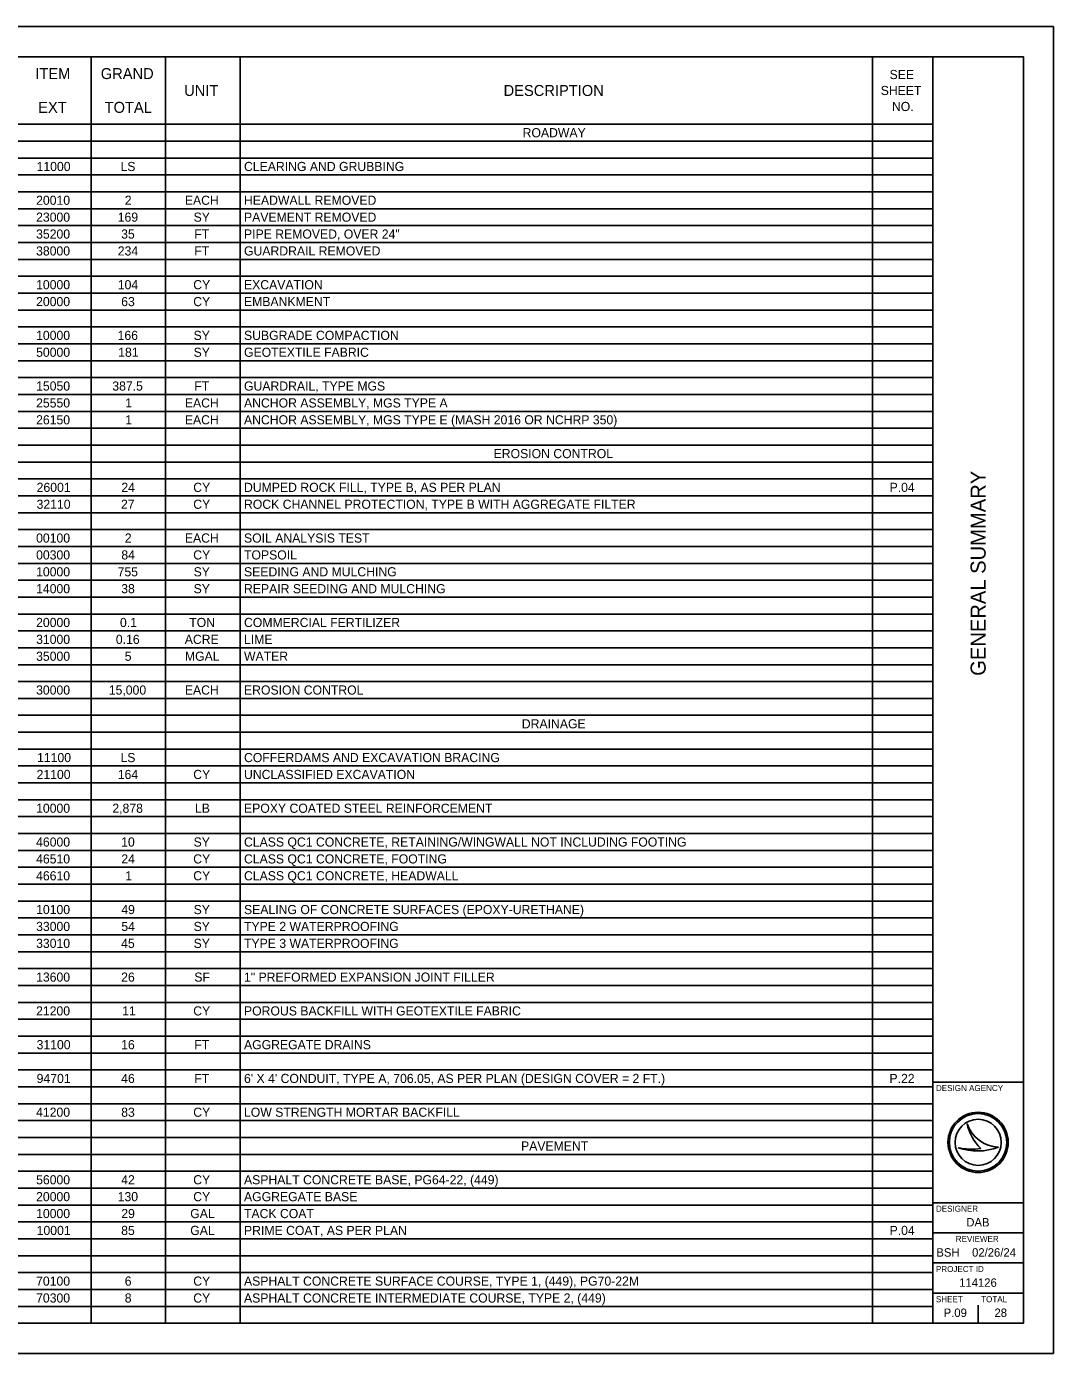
# Model space of a CAD drawing. Extents: x 0 to 34, y 0 to 22.
# Drawn here: x 16.96 to 34, y 0 to 22 of the extents above; entities that cross this region are included whole.
import ezdxf

# ---------------------------------------------------------------- set-up
doc = ezdxf.new("R2010")
doc.units = 0
for name, color, linetype in [('SH_Border', 7, 'Continuous'), ('SH_Cut_Line', 7, 'Continuous'), ('SH_Data', 7, 'Continuous'), ('SH_Text', 7, 'Continuous')]:
    doc.layers.add(name, color=color, linetype=linetype)

msp = doc.modelspace()

# ---------------------------------------------------------------- linework, layer by layer
at = {"layer": 'SH_Border'}
for p, q in [((32, 0.5), (32, 21.5)), ((32, 4.5), (33.5, 4.5)), ((32, 2.5), (33.5, 2.5)), ((32, 2), (33.5, 2)), ((32, 1.5), (33.5, 1.5)), ((32, 1), (33.5, 1))]:
    msp.add_line(p, q, dxfattribs=at)
msp.add_lwpolyline([(1.5, 21.5), (33.5, 21.5), (33.5, 0.5), (1.5, 0.5)], close=True, dxfattribs=at)
at = {"layer": 'SH_Cut_Line'}
msp.add_lwpolyline([(0, 0), (34, 0), (34, 22), (0, 22)], close=True, dxfattribs=at)
at = {"layer": 'SH_Data'}
for p, q in [((32.567, 3.81), (32.567, 3.81)), ((32.417, 3.41), (32.417, 3.41)), ((32.75, 3.5), (32.75, 3.5)), ((33.087, 3.419), (33.087, 3.419)), ((32.375, 0.675), (32.375, 0.675)), ((32.75, 0.5), (32.75, 0.8))]:
    msp.add_line(p, q, dxfattribs=at)
for radius in [0.5, 0.477, 0.477, 0.382]:
    msp.add_circle((32.75, 3.5), radius, dxfattribs=at)
for centre, radius, start, end in [((33.116, 3.998), 0.58, 198.9257, 198.9319), ((33.347, 3.97), 0.796, 191.6379, 191.6421), ((33.116, 3.998), 0.58, 198.9319, 267.1657), ((33.347, 3.97), 0.796, 191.6421, 226.0947), ((32.739, 4.37), 1.013, 251.4576, 290.0832), ((32.648, 4.654), 1.266, 259.4964, 259.4995), ((32.739, 4.37), 1.013, 251.4527, 251.4576), ((32.648, 4.654), 1.266, 259.4995, 276.6672)]:
    msp.add_arc(centre, radius, start, end, dxfattribs=at)
at = {"layer": 'SH_Text'}
for p, q in [((1.5, 21.5), (32, 21.5)), ((18.035, 21.5), (18.035, 0.5)), ((19.27, 21.5), (19.27, 0.5)), ((20.505, 21.5), (20.505, 0.5)), ((30.995, 21.5), (30.995, 0.5)), ((32, 21.5), (32, 0.5)), ((1.5, 20.38), (32, 20.38)), ((1.5, 20.1), (32, 20.1)), ((1.5, 19.82), (32, 19.82)), ((1.5, 19.54), (32, 19.54)), ((1.5, 19.26), (32, 19.26)), ((1.5, 18.98), (32, 18.98)), ((1.5, 18.7), (32, 18.7)), ((1.5, 18.42), (32, 18.42)), ((1.5, 18.14), (32, 18.14)), ((1.5, 17.86), (32, 17.86)), ((1.5, 17.58), (32, 17.58)), ((1.5, 17.3), (32, 17.3)), ((1.5, 17.02), (32, 17.02)), ((1.5, 16.74), (32, 16.74)), ((1.5, 16.46), (32, 16.46)), ((1.5, 16.18), (32, 16.18)), ((1.5, 15.9), (32, 15.9)), ((1.5, 15.62), (32, 15.62)), ((1.5, 15.34), (32, 15.34)), ((1.5, 15.06), (32, 15.06)), ((1.5, 14.78), (32, 14.78)), ((1.5, 14.5), (32, 14.5)), ((1.5, 14.22), (32, 14.22)), ((1.5, 13.94), (32, 13.94)), ((1.5, 13.66), (32, 13.66)), ((1.5, 13.38), (32, 13.38)), ((1.5, 13.1), (32, 13.1)), ((1.5, 12.82), (32, 12.82)), ((1.5, 12.54), (32, 12.54)), ((1.5, 12.26), (32, 12.26)), ((1.5, 11.98), (32, 11.98)), ((1.5, 11.7), (32, 11.7)), ((1.5, 11.42), (32, 11.42)), ((1.5, 11.14), (32, 11.14)), ((1.5, 10.86), (32, 10.86)), ((1.5, 10.58), (32, 10.58)), ((1.5, 10.3), (32, 10.3)), ((1.5, 10.02), (32, 10.02)), ((1.5, 9.74), (32, 9.74)), ((1.5, 9.46), (32, 9.46)), ((1.5, 9.18), (32, 9.18)), ((1.5, 8.9), (32, 8.9)), ((1.5, 8.62), (32, 8.62)), ((1.5, 8.34), (32, 8.34)), ((1.5, 8.06), (32, 8.06)), ((1.5, 7.78), (32, 7.78)), ((1.5, 7.5), (32, 7.5)), ((1.5, 7.22), (32, 7.22)), ((1.5, 6.94), (32, 6.94)), ((1.5, 6.66), (32, 6.66)), ((1.5, 6.38), (32, 6.38)), ((1.5, 6.1), (32, 6.1)), ((1.5, 5.82), (32, 5.82)), ((1.5, 5.54), (32, 5.54)), ((1.5, 5.26), (32, 5.26)), ((1.5, 4.98), (32, 4.98)), ((1.5, 4.7), (32, 4.7)), ((1.5, 4.42), (32, 4.42)), ((1.5, 4.14), (32, 4.14)), ((1.5, 3.86), (32, 3.86)), ((1.5, 3.58), (32, 3.58)), ((1.5, 3.3), (32, 3.3)), ((1.5, 3.02), (32, 3.02)), ((1.5, 2.74), (32, 2.74)), ((1.5, 2.46), (32, 2.46)), ((1.5, 2.18), (32, 2.18)), ((1.5, 1.9), (32, 1.9)), ((1.5, 1.62), (32, 1.62)), ((1.5, 1.34), (32, 1.34)), ((1.5, 1.06), (32, 1.06)), ((1.5, 0.78), (32, 0.78)), ((1.5, 0.5), (32, 0.5))]:
    msp.add_line(p, q, dxfattribs=at)

# ---------------------------------------------------------------- texts
at = {"layer": 'SH_Data'}
msp.add_text('GENERAL SUMMARY', height=0.25, rotation=90, dxfattribs=at).set_placement((32.875, 11.235))
for s, height, p in [('DESIGN AGENCY', 0.1, (32.05, 4.35)), ('DESIGNER', 0.1, (32.05, 2.35)), ('DAB', 0.14, (32.554, 2.105)), ('REVIEWER', 0.1, (32.378, 1.85)), ('BSH', 0.14, (32.057, 1.605)), ('02/26/24', 0.14, (32.649, 1.605)), ('PROJECT ID', 0.1, (32.05, 1.35)), ('114126', 0.14, (32.435, 1.105)), ('SHEET', 0.1, (32.05, 0.85)), ('TOTAL', 0.1, (32.8, 0.85)), ('P.09', 0.14, (32.178, 0.605)), ('28', 0.14, (33.021, 0.605))]:
    msp.add_text(s, height=height, dxfattribs=at).set_placement(p)
at = {"layer": 'SH_Text'}
for s, height, p in [('ITEM', 0.1818, (17.109, 21.129)), ('GRAND', 0.1818, (18.195, 21.129)), ('SEE ', 0.1515, (31.281, 21.129)), ('UNIT', 0.1818, (19.578, 20.849)), ('DESCRIPTION', 0.18184, (24.878, 20.849)), ('SHEET ', 0.1515, (31.134, 20.864)), ('EXT', 0.1818, (17.157, 20.569)), ('TOTAL', 0.1818, (18.259, 20.569)), ('NO.', 0.1515, (31.32, 20.599)), ('ROADWAY', 0.1515, (25.193, 20.164)), ('11000', 0.1515, (17.13, 19.604)), ('LS', 0.1515, (18.522, 19.604)), ('CLEARING AND GRUBBING', 0.15153, (20.571, 19.604)), ('20010', 0.1515, (17.122, 19.044)), ('2', 0.152, (18.593, 19.044)), ('EACH', 0.1515, (19.59, 19.044)), ('HEADWALL REMOVED', 0.15153, (20.571, 19.044)), ('23000', 0.1515, (17.122, 18.764)), ('169', 0.1515, (18.476, 18.764)), ('SY', 0.1515, (19.735, 18.764)), ('PAVEMENT REMOVED', 0.15153, (20.571, 18.764)), ('35200', 0.1515, (17.122, 18.484)), ('35', 0.1515, (18.533, 18.484)), ('FT', 0.1515, (19.747, 18.484)), ('PIPE REMOVED, OVER 24"', 0.15153, (20.571, 18.484)), ('38000', 0.1515, (17.122, 18.204)), ('234', 0.1515, (18.477, 18.204)), ('FT', 0.1515, (19.747, 18.204)), ('GUARDRAIL REMOVED', 0.15153, (20.571, 18.204)), ('10000', 0.1515, (17.122, 17.644)), ('104', 0.1515, (18.477, 17.644)), ('CY', 0.1515, (19.729, 17.644)), ('EXCAVATION', 0.1515, (20.571, 17.644)), ('20000', 0.1515, (17.122, 17.364)), ('63', 0.1515, (18.534, 17.364)), ('CY', 0.1515, (19.729, 17.364)), ('EMBANKMENT', 0.1515, (20.571, 17.364)), ('10000', 0.1515, (17.122, 16.804)), ('166', 0.1515, (18.474, 16.804)), ('SY', 0.1515, (19.735, 16.804)), ('SUBGRADE COMPACTION', 0.15153, (20.571, 16.804)), ('50000', 0.1515, (17.122, 16.524)), ('181', 0.1515, (18.484, 16.524)), ('SY', 0.1515, (19.735, 16.524)), ('GEOTEXTILE FABRIC', 0.15153, (20.571, 16.524)), ('15050', 0.1515, (17.122, 15.964)), ('387.5', 0.1515, (18.386, 15.964)), ('FT', 0.1515, (19.747, 15.964)), ('GUARDRAIL, TYPE MGS', 0.15153, (20.571, 15.964)), ('25550', 0.1515, (17.122, 15.684)), ('1', 0.152, (18.601, 15.684)), ('EACH', 0.1515, (19.59, 15.684)), ('ANCHOR ASSEMBLY, MGS TYPE A', 0.15153, (20.571, 15.684)), ('26150', 0.1515, (17.122, 15.404)), ('1', 0.152, (18.601, 15.404)), ('EACH', 0.1515, (19.59, 15.404)), ('ANCHOR ASSEMBLY, MGS TYPE E (MASH 2016 OR NCHRP 350)', 0.15153, (20.571, 15.404)), ('EROSION CONTROL', 0.15153, (24.712, 14.844)), ('26001', 0.1515, (17.131, 14.284)), ('24', 0.1515, (18.536, 14.284)), ('CY', 0.1515, (19.729, 14.284)), ('DUMPED ROCK FILL, TYPE B, AS PER PLAN', 0.15153, (20.571, 14.284)), ('P.04', 0.1515, (31.281, 14.284)), ('32110', 0.1515, (17.13, 14.004)), ('27', 0.1515, (18.53, 14.004)), ('CY', 0.1515, (19.729, 14.004)), ('ROCK CHANNEL PROTECTION, TYPE B WITH AGGREGATE FILTER', 0.15153, (20.571, 14.004)), ('00100', 0.1515, (17.122, 13.444)), ('2', 0.152, (18.593, 13.444)), ('EACH', 0.1515, (19.59, 13.444)), ('SOIL ANALYSIS TEST', 0.15153, (20.571, 13.444)), ('00300', 0.1515, (17.122, 13.164)), ('84', 0.1515, (18.536, 13.164)), ('CY', 0.1515, (19.729, 13.164)), ('TOPSOIL', 0.1515, (20.571, 13.164)), ('10000', 0.1515, (17.122, 12.884)), ('755', 0.1515, (18.474, 12.884)), ('SY', 0.1515, (19.735, 12.884)), ('SEEDING AND MULCHING', 0.15153, (20.571, 12.884)), ('14000', 0.1515, (17.122, 12.604)), ('38', 0.1515, (18.534, 12.604)), ('SY', 0.1515, (19.735, 12.604)), ('REPAIR SEEDING AND MULCHING', 0.15153, (20.571, 12.604)), ('20000', 0.1515, (17.122, 12.044)), ('0.1', 0.1515, (18.513, 12.044)), ('TON', 0.1515, (19.662, 12.044)), ('COMMERCIAL FERTILIZER', 0.15153, (20.571, 12.044)), ('31000', 0.1515, (17.122, 11.764)), ('0.16', 0.1515, (18.445, 11.764)), ('ACRE', 0.1515, (19.588, 11.764)), ('LIME', 0.1515, (20.571, 11.764)), ('35000', 0.1515, (17.122, 11.484)), ('5', 0.152, (18.592, 11.484)), ('MGAL', 0.1515, (19.591, 11.484)), ('WATER', 0.1515, (20.571, 11.484)), ('30000', 0.1515, (17.122, 10.924)), ('15,000', 0.1515, (18.328, 10.924)), ('EACH', 0.1515, (19.59, 10.924)), ('EROSION CONTROL', 0.15153, (20.571, 10.924)), ('DRAINAGE', 0.1515, (25.18, 10.364)), ('11100', 0.1515, (17.138, 9.804)), ('LS', 0.1515, (18.522, 9.804)), ('COFFERDAMS AND EXCAVATION BRACING', 0.15153, (20.571, 9.804)), ('21100', 0.1515, (17.13, 9.524)), ('164', 0.1515, (18.477, 9.524)), ('CY', 0.1515, (19.729, 9.524)), ('UNCLASSIFIED EXCAVATION', 0.15153, (20.571, 9.524)), ('10000', 0.1515, (17.122, 8.964)), ('2,878', 0.1515, (18.387, 8.964)), ('LB', 0.1515, (19.758, 8.964)), ('EPOXY COATED STEEL REINFORCEMENT', 0.15153, (20.571, 8.964)), ('46000', 0.1515, (17.122, 8.404)), ('10', 0.1515, (18.533, 8.404)), ('SY', 0.1515, (19.735, 8.404)), ('CLASS QC1 CONCRETE, RETAINING/WINGWALL NOT INCLUDING FOOTING', 0.15153, (20.571, 8.404)), ('46510', 0.1515, (17.122, 8.124)), ('24', 0.1515, (18.536, 8.124)), ('CY', 0.1515, (19.729, 8.124)), ('CLASS QC1 CONCRETE, FOOTING', 0.15153, (20.571, 8.124)), ('46610', 0.1515, (17.122, 7.844)), ('1', 0.152, (18.601, 7.844)), ('CY', 0.1515, (19.729, 7.844)), ('CLASS QC1 CONCRETE, HEADWALL', 0.15153, (20.571, 7.844)), ('10100', 0.1515, (17.122, 7.284)), ('49', 0.1515, (18.535, 7.284)), ('SY', 0.1515, (19.735, 7.284)), ('SEALING OF CONCRETE SURFACES (EPOXY-URETHANE)', 0.15153, (20.571, 7.284)), ('33000', 0.1515, (17.122, 7.004)), ('54', 0.1515, (18.536, 7.004)), ('SY', 0.1515, (19.735, 7.004)), ('TYPE 2 WATERPROOFING', 0.15153, (20.571, 7.004)), ('33010', 0.1515, (17.122, 6.724)), ('45', 0.1515, (18.533, 6.724)), ('SY', 0.1515, (19.735, 6.724)), ('TYPE 3 WATERPROOFING', 0.15153, (20.571, 6.724)), ('13600', 0.1515, (17.122, 6.164)), ('26', 0.1515, (18.533, 6.164)), ('SF', 0.1515, (19.747, 6.164)), ('1" PREFORMED EXPANSION JOINT FILLER', 0.15153, (20.571, 6.164)), ('21200', 0.1515, (17.122, 5.604)), ('11', 0.1515, (18.55, 5.604)), ('CY', 0.1515, (19.729, 5.604)), ('POROUS BACKFILL WITH GEOTEXTILE FABRIC', 0.15153, (20.571, 5.604)), ('31100', 0.1515, (17.13, 5.044)), ('16', 0.1515, (18.533, 5.044)), ('FT', 0.1515, (19.747, 5.044)), ('AGGREGATE DRAINS', 0.15153, (20.571, 5.044)), ('94701', 0.1515, (17.131, 4.484)), ('46', 0.1515, (18.533, 4.484)), ('FT', 0.1515, (19.747, 4.484)), ("6' X 4' CONDUIT, TYPE A, 706.05, AS PER PLAN (DESIGN COVER = 2 FT.)", 0.15153, (20.571, 4.484)), ('P.22', 0.1515, (31.279, 4.484)), ('41200', 0.1515, (17.122, 3.924)), ('83', 0.1515, (18.534, 3.924)), ('CY', 0.1515, (19.729, 3.924)), ('LOW STRENGTH MORTAR BACKFILL', 0.15153, (20.571, 3.924)), ('PAVEMENT', 0.1515, (25.167, 3.364)), ('56000', 0.1515, (17.122, 2.804)), ('42', 0.1515, (18.534, 2.804)), ('CY', 0.1515, (19.729, 2.804)), ('ASPHALT CONCRETE BASE, PG64-22, (449)', 0.15153, (20.571, 2.804)), ('20000', 0.1515, (17.122, 2.524)), ('130', 0.1515, (18.475, 2.524)), ('CY', 0.1515, (19.729, 2.524)), ('AGGREGATE BASE', 0.15153, (20.571, 2.524)), ('10000', 0.1515, (17.122, 2.244)), ('29', 0.1515, (18.535, 2.244)), ('GAL', 0.1515, (19.679, 2.244)), ('TACK COAT', 0.1515, (20.571, 2.244)), ('10001', 0.1515, (17.131, 1.964)), ('85', 0.1515, (18.533, 1.964)), ('GAL', 0.1515, (19.679, 1.964)), ('PRIME COAT, AS PER PLAN', 0.15153, (20.571, 1.964)), ('P.04', 0.1515, (31.281, 1.964)), ('70100', 0.1515, (17.122, 1.124)), ('6', 0.152, (18.592, 1.124)), ('CY', 0.1515, (19.729, 1.124)), ('ASPHALT CONCRETE SURFACE COURSE, TYPE 1, (449), PG70-22M', 0.15153, (20.571, 1.124)), ('70300', 0.1515, (17.122, 0.844)), ('8', 0.152, (18.592, 0.844)), ('CY', 0.1515, (19.729, 0.844)), ('ASPHALT CONCRETE INTERMEDIATE COURSE, TYPE 2, (449)', 0.15153, (20.571, 0.844))]:
    msp.add_text(s, height=height, dxfattribs=at).set_placement(p)

doc.saveas('drawing.dxf')
